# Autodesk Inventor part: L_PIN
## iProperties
Author: GJOHNST2
Shininess: 20.0
Length Units: 11272
Angle Units: 11286
Time Units: 11279
Mass Units: 11290
Length Display Precision: 3
Angle Display Precision: 2
Compacted: True
PropertySet Name: _Private Model Information
Created: 2001-11
Part Number: L_PIN
Document SubType Name: Modeling
Designer: GJOHNST2
Control State: 0
Master: False
Checked Out: False
PropertySet Name: Design Tracking Control
Density: 0.0
Volumn: 0.0
Area: 0.0
PropertySet Name: Model Information
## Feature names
1. Extrusion1
2. Extrusion2
3. Fillet1
4. Extrusion3
5. Fillet2
